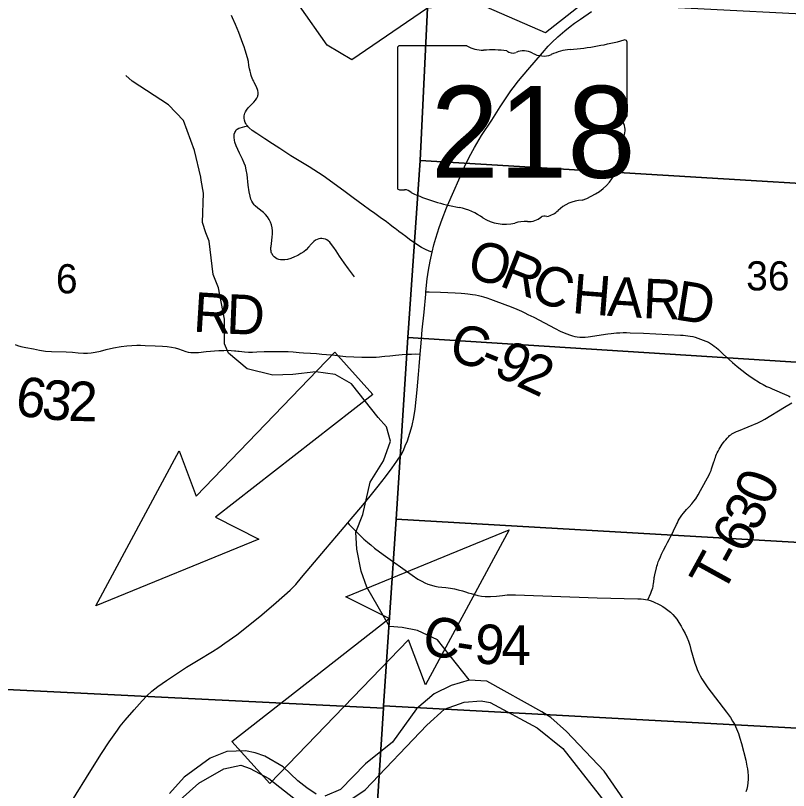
# Model space of a CAD drawing. Extents: x 396.2 to 468.4, y 232.6 to 279.1.
# Drawn here: x 421.28 to 422.39, y 275.126 to 276.238 of the extents above; entities that cross this region are included whole.
import ezdxf

# ---------------------------------------------------------------- set-up
doc = ezdxf.new("R2010")
doc.units = 0
for name, color, linetype in [('GM_X_County_Road', 7, 'Continuous'), ('GM_X_County_Road_Text', 7, 'Continuous'), ('GM_X_Major_River', 7, 'Continuous'), ('GM_X_Minor_River', 7, 'Continuous'), ('GM_X_Section', 7, 'Continuous'), ('GM_X_Section_Text', 7, 'Continuous'), ('GM_X_State_Location', 7, 'Continuous'), ('GM_X_State_Route', 7, 'Continuous'), ('GM_X_State_Shield', 7, 'Continuous'), ('GM_X_Township_Road', 7, 'Continuous'), ('GM_X_Township_Road_Text', 7, 'Continuous'), ('TX_P_1', 7, 'Continuous')]:
    doc.layers.add(name, color=color, linetype=linetype)

msp = doc.modelspace()

# ---------------------------------------------------------------- linework, layer by layer
at = {"layer": 'GM_X_County_Road'}
for points in [[(421.8269, 275.9308), (421.8253, 275.932), (421.8219, 275.9345), (421.82, 275.9359), (421.8172, 275.938), (421.8123, 275.9419), (421.8034, 275.9483), (421.7958, 275.9539), (421.7883, 275.9595), (421.7789, 275.9661), (421.7647, 275.9763), (421.753, 275.9849), (421.7354, 275.9981), (421.7217, 276.0081), (421.7015, 276.0212), (421.6848, 276.0308), (421.6752, 276.037), (421.6593, 276.0472), (421.6489, 276.0541), (421.6379, 276.0611), (421.6265, 276.0687), (421.6197, 276.0733), (421.6154, 276.077), (421.6139, 276.0784), (421.6128, 276.0797), (421.6115, 276.0815), (421.6106, 276.0831), (421.6098, 276.0847), (421.6085, 276.0881), (421.608, 276.091), (421.608, 276.094), (421.6085, 276.0962), (421.609, 276.0978), (421.6099, 276.0999), (421.6113, 276.1025), (421.614, 276.1057), (421.6157, 276.1075), (421.6222, 276.114), (421.6244, 276.1166), (421.6262, 276.1193), (421.6275, 276.1216), (421.6278, 276.1224), (421.628, 276.1233), (421.6283, 276.125), (421.6284, 276.1279), (421.628, 276.1303), (421.6275, 276.132), (421.6265, 276.1344), (421.6244, 276.1388), (421.6227, 276.1421), (421.6219, 276.1438), (421.6207, 276.146), (421.6189, 276.1505), (421.6184, 276.1522), (421.6178, 276.1546), (421.6169, 276.1581), (421.616, 276.1617), (421.6151, 276.1665), (421.6142, 276.172), (421.6129, 276.1772), (421.6097, 276.1884), (421.6081, 276.193), (421.6063, 276.1982), (421.6004, 276.2138), (421.5958, 276.2253), (421.5916, 276.235), (421.5902, 276.2382)], [(421.8779, 275.8984), (421.8738, 275.9), (421.8687, 275.9022), (421.8628, 275.9054), (421.8517, 275.9124), (421.8457, 275.9166), (421.8401, 275.9208), (421.8351, 275.9248), (421.8301, 275.9284), (421.8269, 275.9308)], [(421.8691, 275.8417), (421.8735, 275.8416), (421.8899, 275.841), (421.9112, 275.8402), (421.9199, 275.8397), (421.9247, 275.8393), (421.9294, 275.8388), (421.9327, 275.8384), (421.9361, 275.8379), (421.9403, 275.8372), (421.9447, 275.8363), (421.9482, 275.8355), (421.9519, 275.8344), (421.9565, 275.833), (421.9619, 275.8311), (421.9694, 275.8284), (421.9915, 275.8199), (421.9996, 275.8165), (422.0062, 275.8136), (422.0113, 275.8112), (422.0154, 275.8092), (422.0198, 275.8071), (422.0239, 275.805), (422.0547, 275.789), (422.0619, 275.7853), (422.0673, 275.7829), (422.0713, 275.7812), (422.0751, 275.7799), (422.0795, 275.7786), (422.0829, 275.7777), (422.0863, 275.7771), (422.0899, 275.7767), (422.0938, 275.7765), (422.0977, 275.7767), (422.102, 275.777), (422.1302, 275.7811), (422.1352, 275.7817), (422.139, 275.7822), (422.1428, 275.7826), (422.1474, 275.7828), (422.152, 275.783), (422.1568, 275.783), (422.1622, 275.7829), (422.1816, 275.7822), (422.2346, 275.7793), (422.2383, 275.7792), (422.2418, 275.7789), (422.2452, 275.7785), (422.2486, 275.778), (422.2521, 275.7773), (422.2556, 275.7764), (422.2593, 275.7753), (422.2634, 275.7738), (422.2671, 275.7724), (422.271, 275.7707), (422.2746, 275.7691), (422.2778, 275.7672), (422.2803, 275.7656), (422.283, 275.7638), (422.2859, 275.7615), (422.289, 275.7587), (422.2959, 275.7519), (422.3093, 275.7401), (422.316, 275.7344), (422.3294, 275.7239), (422.3328, 275.7213), (422.3374, 275.7181), (422.3495, 275.7105), (422.3534, 275.7084), (422.3582, 275.7059), (422.3621, 275.7041), (422.366, 275.7023), (422.387, 275.6931), (422.3894, 275.6921), (422.3919, 275.6911)], [(421.7568, 275.51), (421.759, 275.5077), (421.7765, 275.4899), (421.78, 275.4865), (421.7823, 275.4845), (421.7855, 275.4818), (421.7898, 275.4783), (421.7953, 275.4738), (421.8075, 275.4647), (421.8495, 275.4349), (421.8577, 275.4294), (421.863, 275.4262), (421.8675, 275.4238), (421.872, 275.422), (421.8771, 275.4204), (421.882, 275.4192), (421.8866, 275.4184), (421.8919, 275.4177), (421.8977, 275.417), (421.9042, 275.4162), (421.9099, 275.4152), (421.9156, 275.414), (421.9217, 275.4124), (421.926, 275.4111), (421.9298, 275.4098), (421.9338, 275.4086), (421.9387, 275.4072), (421.9437, 275.4059), (421.9487, 275.405), (421.9541, 275.4045), (421.9617, 275.4045), (421.9704, 275.405), (421.979, 275.4058), (421.9858, 275.4065), (421.9916, 275.4066), (421.9976, 275.4065), (422.1149, 275.4023), (422.1731, 275.4011), (422.1782, 275.4009), (422.1813, 275.4007), (422.1841, 275.4002), (422.1878, 275.3993), (422.1912, 275.3984), (422.1946, 275.3972), (422.1978, 275.3959), (422.2018, 275.394), (422.205, 275.3922), (422.2091, 275.3898), (422.2127, 275.3875), (422.2165, 275.3846), (422.2201, 275.3817), (422.2233, 275.3786), (422.2263, 275.3753), (422.2292, 275.3716), (422.2322, 275.3669), (422.2354, 275.3619), (422.2381, 275.3571), (422.2411, 275.3512), (422.2435, 275.3458), (422.2458, 275.3401), (422.2477, 275.3343), (422.2496, 275.3282), (422.2552, 275.3086), (422.2568, 275.3039), (422.2584, 275.2995), (422.2602, 275.2953), (422.2626, 275.2906), (422.2653, 275.2859), (422.2679, 275.2819), (422.274, 275.2734), (422.3005, 275.2383), (422.3036, 275.2343), (422.3063, 275.2304), (422.3094, 275.2256), (422.3119, 275.221), (422.3149, 275.2144), (422.3176, 275.2076), (422.3198, 275.2011), (422.3221, 275.1934), (422.3281, 275.1694), (422.3299, 275.161), (422.3307, 275.1568), (422.3313, 275.1526), (422.3317, 275.1469), (422.3318, 275.1419), (422.3313, 275.1369), (422.3306, 275.1325), (422.3296, 275.128), (422.3283, 275.1239)]]:
    msp.add_lwpolyline(points, dxfattribs=at)
at = {"layer": 'GM_X_Major_River'}
for points in [[(422.1633, 275.0982), (422.1248, 275.1534), (422.0708, 275.2107), (422.0484, 275.2307), (422.0355, 275.2389), (421.9566, 275.2829), (421.9312, 275.2842), (421.9052, 275.2765), (421.8807, 275.2646), (421.8555, 275.2432), (421.8209, 275.1952), (421.7825, 275.1639), (421.7464, 275.1272), (421.7241, 275.1176)], [(421.7454, 275.1026), (421.782, 275.1267), (421.8703, 275.2198), (421.8959, 275.2427), (421.9239, 275.2527), (421.9484, 275.2547), (421.9613, 275.2522), (422.0288, 275.2158), (422.0657, 275.186), (422.1369, 275.0954)], [(421.7113, 275.1206), (421.698, 275.1296), (421.6854, 275.1398), (421.6642, 275.1597), (421.638, 275.1751), (421.624, 275.18), (421.6103, 275.1826), (421.5831, 275.182), (421.5593, 275.1724), (421.522, 275.1449), (421.501, 275.1216)], [(421.5165, 275.1126), (421.5433, 275.1363), (421.5791, 275.157), (421.6036, 275.162), (421.6169, 275.1576), (421.6434, 275.1429), (421.6886, 275.1075)]]:
    msp.add_lwpolyline(points, dxfattribs=at)
at = {"layer": 'GM_X_Minor_River'}
for points in [[(422.2995, 276.3228), (422.2267, 276.2876), (422.1231, 276.2784), (422.0405, 276.2135), (421.945, 276.2548), (421.8715, 276.2488), (421.7627, 276.1746), (421.7271, 276.1955), (421.6877, 276.2521)], [(421.7624, 275.7094), (421.7389, 275.7227), (421.7109, 275.7269), (421.6779, 275.723), (421.6491, 275.7222), (421.6127, 275.7313), (421.5858, 275.7537), (421.5798, 275.767), (421.5798, 275.8024), (421.5711, 275.8473), (421.5635, 275.8663), (421.5578, 275.9145), (421.5533, 275.9263), (421.5484, 275.9411), (421.5499, 275.983), (421.5465, 276.002), (421.5461, 276.0062), (421.537, 276.0442), (421.5211, 276.0875), (421.4995, 276.1099), (421.4472, 276.1437), (421.4381, 276.1521)], [(421.931, 275.2846), (421.8856, 275.3423), (421.8569, 275.3553), (421.8351, 275.3598), (421.8166, 275.3612), (421.7843, 275.4176), (421.776, 275.4407), (421.7697, 275.472), (421.7686, 275.4964), (421.7784, 275.5219), (421.7889, 275.5683), (421.808, 275.5992), (421.8183, 275.6273), (421.8125, 275.648), (421.8004, 275.6613), (421.7623, 275.7095)]]:
    msp.add_lwpolyline(points, dxfattribs=at)
at = {"layer": 'GM_X_Section'}
for points in [[(420.8243, 276.321), (421.8725, 276.2694), (421.8607, 276.0303), (421.8429, 275.7758), (421.8262, 275.5154), (421.8083, 275.2473), (421.8081, 275.2441), (420.7452, 275.2968)], [(421.8725, 276.2694), (422.1563, 276.2535), (422.9042, 276.2154), (422.8899, 275.9679), (421.8607, 276.0303)], [(422.8899, 275.9679), (422.875, 275.7105), (421.8429, 275.7758), (421.8607, 276.0303)], [(421.8429, 275.7758), (422.875, 275.7105), (422.8603, 275.4553), (421.8262, 275.5154)], [(422.8603, 275.4553), (422.8451, 275.1916), (421.8083, 275.2473), (421.8262, 275.5154)], [(420.7452, 275.2968), (421.8081, 275.2441), (421.7928, 275.0058), (421.7775, 274.755), (421.761, 274.4956), (421.7452, 274.2485), (420.6845, 274.2907)], [(421.8083, 275.2473), (422.8451, 275.1916), (422.8297, 274.9443), (421.7928, 275.0058), (421.8081, 275.2441)]]:
    msp.add_lwpolyline(points, close=True, dxfattribs=at)
at = {"layer": 'GM_X_State_Route'}
msp.add_lwpolyline([(421.3606, 275.1105), (421.3879, 275.1546), (421.4032, 275.1792), (421.4142, 275.1957), (421.4261, 275.2124), (421.4303, 275.218), (421.4371, 275.2266), (421.4501, 275.2416), (421.4615, 275.2546), (421.4683, 275.2618), (421.4755, 275.2686), (421.4842, 275.2753), (421.4965, 275.2838), (421.5255, 275.303), (421.5419, 275.3131), (421.5626, 275.3255), (421.5716, 275.3312), (421.5802, 275.3373), (421.5977, 275.3495), (421.6093, 275.3582), (421.6333, 275.3781), (421.6543, 275.3957), (421.6743, 275.4135), (421.6822, 275.4217), (421.6907, 275.4314), (421.704, 275.4472), (421.7247, 275.472), (421.7411, 275.4915), (421.7568, 275.51), (421.762, 275.516), (421.7783, 275.5355), (421.7888, 275.5485), (421.8004, 275.5628), (421.8109, 275.5761), (421.8205, 275.5888), (421.8275, 275.5987), (421.8343, 275.6093), (421.8373, 275.6152), (421.8395, 275.6204), (421.8426, 275.6279), (421.8462, 275.6388), (421.8494, 275.6495), (421.8517, 275.6612), (421.8534, 275.6732), (421.8563, 275.7008), (421.8582, 275.7227), (421.8592, 275.7342), (421.8608, 275.7521), (421.8623, 275.7679), (421.8639, 275.787), (421.8664, 275.8125), (421.8688, 275.8382), (421.8691, 275.8417), (421.8711, 275.8602), (421.8728, 275.8725), (421.8751, 275.8856), (421.8779, 275.8984), (421.8805, 275.9088), (421.8831, 275.9188), (421.8881, 275.9341), (421.8924, 275.9461), (421.8988, 275.962), (421.9072, 275.9816), (421.918, 276.0066), (421.9245, 276.0211), (421.9313, 276.0348), (421.9389, 276.0486), (421.949, 276.0658), (421.9635, 276.0881), (421.9758, 276.1073), (421.9911, 276.1299), (421.9944, 276.1345), (422.0021, 276.1444), (422.0155, 276.1603), (422.0364, 276.1846), (422.0448, 276.194), (422.0499, 276.1994), (422.0584, 276.2075), (422.0685, 276.2163), (422.0761, 276.2224), (422.0825, 276.2273), (422.0909, 276.2331), (422.1066, 276.244)], dxfattribs=at)
at = {"layer": 'GM_X_State_Shield'}
for p, q in [((422.1579, 276.0951), (422.1579, 276.1998)), ((421.8283, 276.1914), (421.8283, 275.9912)), ((421.928, 276.1948), (421.8315, 276.1948)), ((422.1578, 276.0951), (422.1579, 276.0951))]:
    msp.add_line(p, q, dxfattribs=at)
for centre, major_axis, start_param, end_param in [((422.0405, 276.4676), (0.3495, 0), 4.814394, 5.042369), ((422.1542, 276.2002), (0.00367, 0), 6.141152, 7.989035), ((421.8321, 276.1918), (0.00382, 0), 1.712693, 3.28349), ((421.951, 276.218), (0.037, 0), 4.042523, 4.731795), ((421.9633, 276.0824), (0.133, 0), 1.404758, 1.657858), ((422.0092, 276.1697), (0.0222, 0), 0.950623, 2.079405), ((422.085, 276.1337), (0.0703, 0), 1.699011, 2.107814), ((421.9935, 276.1928), (0.0107, 0), 3.836095, 5.185415), ((422.0379, 276.2014), (0.0267, 0), 4.081561, 5.145723), ((422.157, 276.0874), (0.00568, 0), 1.883978, 3.671073), ((422.1539, 276.0947), (0.00393, 0), 5.05454, 6.418171), ((422.1209, 276.0742), (0.0341, 0), 5.934695, 6.695948), ((422.171, 276.0513), (0.0248, 0), 2.387724, 3.262537), ((422.06, 276.0379), (0.0874, 0), 5.101752, 6.440018), ((421.8321, 275.9908), (0.00385, 0), 3.00124, 4.508301), ((421.8327, 276.0113), (0.0294, 0), 4.665946, 4.897461), ((421.8387, 275.9797), (0.0106, 0), 0.519207, 1.627899), ((421.9725, 276.1595), (0.2524, 0), 4.195997, 4.488961), ((422.0969, 275.935), (0.0479, 0), 1.647645, 2.488434), ((421.8973, 275.9013), (0.079, 0), 0.823519, 1.323587), ((422.0362, 275.9718), (0.0282, 0), 4.937069, 5.64225), ((421.9827, 275.9787), (0.0501, 0), 4.026481, 4.996735), ((422.0153, 275.9637), (0.0267, 0), 4.691044, 5.507374), ((422.0394, 275.9443), (0.00752, 0), 1.147584, 2.315152), ((422.0116, 275.9095), (0.0412, 0), 1.495662, 1.94098)]:
    msp.add_ellipse(centre, major_axis=major_axis, ratio=0.8, start_param=start_param, end_param=end_param, dxfattribs=at)
at = {"layer": 'GM_X_Township_Road'}
for points in [[(421.7667, 275.8632), (421.7579, 275.8744), (421.7517, 275.8831), (421.7452, 275.8927), (421.74, 275.9005), (421.7371, 275.9052), (421.7337, 275.9096), (421.7309, 275.913), (421.7287, 275.915), (421.7267, 275.9162), (421.7248, 275.9171), (421.7221, 275.9177), (421.7195, 275.918), (421.7176, 275.9181), (421.7152, 275.9176), (421.7129, 275.9167), (421.7107, 275.9155), (421.7082, 275.9137), (421.705, 275.9107), (421.7005, 275.9056), (421.6971, 275.902), (421.6938, 275.8992), (421.6897, 275.8964), (421.6854, 275.8939), (421.6803, 275.8916), (421.6751, 275.8896), (421.6703, 275.8882), (421.6666, 275.8875), (421.6635, 275.8873), (421.6604, 275.8875), (421.658, 275.8879), (421.6551, 275.889), (421.653, 275.8903), (421.6511, 275.8919), (421.6495, 275.8938), (421.6482, 275.8959), (421.6476, 275.8971), (421.6471, 275.8984), (421.6467, 275.9003), (421.6465, 275.9017), (421.6465, 275.9035), (421.6466, 275.9054), (421.6467, 275.9068), (421.6473, 275.9111), (421.6484, 275.92), (421.6488, 275.9246), (421.6487, 275.929), (421.6482, 275.9333), (421.6473, 275.9375), (421.6459, 275.9416), (421.644, 275.9456), (421.6417, 275.9492), (421.639, 275.9526), (421.6358, 275.9556), (421.6279, 275.9616), (421.6241, 275.9648), (421.6224, 275.9666), (421.6206, 275.9691), (421.619, 275.9718), (421.6179, 275.9747), (421.6167, 275.9789), (421.6155, 275.9849), (421.6141, 275.9948), (421.6123, 276.0102), (421.6111, 276.0169), (421.6099, 276.0217), (421.6084, 276.0264), (421.6059, 276.0321), (421.6017, 276.0404), (421.5989, 276.0459), (421.5968, 276.051), (421.595, 276.0563), (421.5942, 276.0593), (421.5936, 276.0629), (421.5936, 276.0661), (421.5939, 276.0679), (421.5946, 276.0702), (421.5955, 276.0719), (421.5969, 276.0739), (421.5983, 276.0751), (421.6003, 276.0763), (421.6025, 276.0771), (421.6056, 276.0779), (421.6091, 276.0789), (421.6128, 276.0797)], [(421.2795, 275.7662), (421.2829, 275.7646), (421.2876, 275.763), (421.2947, 275.7615), (421.3058, 275.7596), (421.3145, 275.758), (421.3231, 275.7566), (421.3318, 275.7561), (421.3526, 275.7554), (421.3618, 275.7548), (421.37, 275.7541), (421.3776, 275.7535), (421.3835, 275.7535), (421.3886, 275.7539), (421.3944, 275.7549), (421.4019, 275.7565), (421.4101, 275.7587), (421.4205, 275.761), (421.4317, 275.7629), (421.4396, 275.7641), (421.447, 275.7647), (421.4543, 275.7649), (421.4593, 275.7648), (421.466, 275.7647), (421.4802, 275.764), (421.4909, 275.7635), (421.4977, 275.7631), (421.5038, 275.7623), (421.5093, 275.7612), (421.514, 275.7598), (421.5193, 275.7579), (421.5245, 275.7561), (421.528, 275.7552), (421.5316, 275.7547), (421.5364, 275.7544), (421.5424, 275.7546), (421.5537, 275.7557), (421.5717, 275.7572), (421.579, 275.7576), (421.5832, 275.7577), (421.5894, 275.7575), (421.5943, 275.7571), (421.5961, 275.757), (421.5992, 275.7566), (421.6011, 275.7565), (421.6085, 275.7556), (421.6146, 275.7551), (421.6171, 275.7551), (421.6202, 275.7551), (421.6263, 275.7555), (421.6369, 275.7559), (421.6435, 275.7561), (421.6531, 275.7561), (421.6608, 275.7561), (421.6663, 275.7561), (421.6714, 275.7559), (421.6786, 275.7553), (421.6829, 275.7549), (421.6872, 275.7546), (421.6934, 275.7542), (421.7032, 275.7534), (421.7119, 275.7529), (421.7196, 275.7523), (421.7265, 275.7518), (421.7345, 275.751), (421.7419, 275.7502), (421.7542, 275.749), (421.7654, 275.7483), (421.7772, 275.7478), (421.7834, 275.7477), (421.792, 275.7476), (421.7975, 275.7478), (421.8023, 275.7483), (421.8058, 275.7487), (421.81, 275.7491), (421.8173, 275.7497), (421.8216, 275.7502), (421.8253, 275.7506), (421.8352, 275.7514), (421.8432, 275.752), (421.8484, 275.7522), (421.8535, 275.7524), (421.8608, 275.7521)], [(422.1878, 275.3993), (422.192, 275.4091), (422.1931, 275.4119), (422.1939, 275.4142), (422.1947, 275.4166), (422.1952, 275.4186), (422.1955, 275.4206), (422.1957, 275.4226), (422.1965, 275.4296), (422.1968, 275.4314), (422.1971, 275.4332), (422.1975, 275.4353), (422.1999, 275.4453), (422.2006, 275.4479), (422.2014, 275.4504), (422.2027, 275.454), (422.204, 275.4571), (422.2056, 275.4611), (422.2073, 275.465), (422.2103, 275.471), (422.2135, 275.477), (422.2159, 275.4816), (422.2184, 275.4862), (422.2208, 275.4909), (422.2233, 275.496), (422.2256, 275.501), (422.2273, 275.5045), (422.2287, 275.5075), (422.2301, 275.5101), (422.2314, 275.5127), (422.2328, 275.5152), (422.2345, 275.518), (422.2365, 275.521), (422.2389, 275.524), (422.2433, 275.5292), (422.2469, 275.5331), (422.2509, 275.5372), (422.2539, 275.5409), (422.2565, 275.5445), (422.2598, 275.55), (422.2634, 275.5565), (422.2756, 275.5788), (422.2767, 275.5811), (422.2777, 275.5833), (422.2785, 275.5853), (422.2792, 275.5875), (422.2825, 275.5978), (422.2831, 275.5997), (422.2838, 275.6019), (422.2846, 275.604), (422.2854, 275.6061), (422.2864, 275.6085), (422.2874, 275.6106), (422.2886, 275.613), (422.2901, 275.6159), (422.2914, 275.6182), (422.2929, 275.6206), (422.2945, 275.623), (422.2962, 275.6253), (422.2978, 275.6274), (422.2994, 275.6292), (422.3014, 275.6315), (422.3037, 275.6339), (422.3051, 275.6352), (422.3067, 275.6364), (422.3084, 275.6376), (422.3103, 275.6388), (422.3122, 275.6399), (422.3148, 275.6411), (422.3178, 275.6423), (422.3457, 275.6535), (422.3486, 275.6549), (422.3512, 275.6563), (422.3556, 275.6589), (422.3837, 275.6759), (422.3945, 275.6824)]]:
    msp.add_lwpolyline(points, dxfattribs=at)
at = {"layer": 'TX_P_1'}
for p, q in [((421.5394, 275.5485), (421.7383, 275.7548)), ((421.7383, 275.7548), (421.7928, 275.6942)), ((421.7928, 275.6942), (421.5668, 275.5182)), ((421.395, 275.391), (421.5148, 275.6136)), ((421.5148, 275.6136), (421.5394, 275.5485)), ((421.5668, 275.5182), (421.629, 275.4867)), ((421.7542, 275.404), (421.9884, 275.4999)), ((421.9884, 275.4999), (421.8686, 275.2774)), ((421.629, 275.4867), (421.395, 275.391)), ((421.8165, 275.3729), (421.7542, 275.404)), ((421.5906, 275.1962), (421.8165, 275.3729)), ((421.844, 275.3423), (421.6451, 275.136)), ((421.8686, 275.2774), (421.844, 275.3423)), ((421.6451, 275.136), (421.5906, 275.1962))]:
    msp.add_line(p, q, dxfattribs=at)

# ---------------------------------------------------------------- texts
at = {"layer": 'GM_X_County_Road_Text'}
for s, rotation, p in [('O', 346.1466, (421.9261, 275.8623)), ('R', 338.1479, (421.9726, 275.8509)), ('C', 337.5053, (422.0158, 275.8336)), ('H', 355.5342, (422.0778, 275.8112)), ('A', 356.3425, (422.1285, 275.8073)), ('R', 357.5012, (422.1797, 275.804)), ('D', 351.0036, (422.2246, 275.8022)), ('C', 346.7769, (421.9002, 275.7425)), ('9', 332.8252, (421.9638, 275.7243)), ('-', 337.9181, (421.9434, 275.7325)), ('2', 334.851, (421.9969, 275.7074)), ('C', 348.1983, (421.8609, 275.3232)), ('9', 355.2721, (421.9373, 275.309)), ('4', 0.07, (421.9773, 275.3059)), ('-', 351.097, (421.9097, 275.3131))]:
    msp.add_text(s, height=0.0568, rotation=rotation, dxfattribs=at).set_placement(p)
at = {"layer": 'GM_X_Section_Text'}
for s, height, p in [('6', 0.0419, (421.3379, 275.8394)), ('36', 0.04186, (422.3288, 275.8436))]:
    msp.add_text(s, height=height, rotation=0, dxfattribs=at).set_placement(p)
at = {"layer": 'GM_X_State_Location'}
for s in ['s', 'r']:
    msp.add_text(s, height=0.000189, dxfattribs=at).set_placement((421.9894, 276.078))
msp.add_text('218', height=0.000189, rotation=0, dxfattribs=at).set_placement((421.9225, 276.0642))
at = {"layer": 'GM_X_State_Shield'}
msp.add_text('218', height=0.13184, dxfattribs=at).set_placement((421.8759, 276.0053))
at = {"layer": 'GM_X_Township_Road_Text'}
for s, rotation, p in [('R', 356.4285, (421.534, 275.7846)), ('D', 357.7398, (421.5819, 275.7816)), ('6', 351.5629, (421.2778, 275.6651)), ('3', 355.2612, (421.3164, 275.6595)), ('2', 358.8557, (421.3551, 275.6564)), ('0', 68.8146, (422.3628, 275.5325)), ('3', 62.6549, (422.344, 275.4954)), ('6', 61.4427, (422.3266, 275.4635)), ('T', 61.1593, (422.2947, 275.4055)), ('-', 61.2133, (422.3153, 275.4428))]:
    msp.add_text(s, height=0.0568, rotation=rotation, dxfattribs=at).set_placement(p)

doc.saveas('drawing.dxf')
